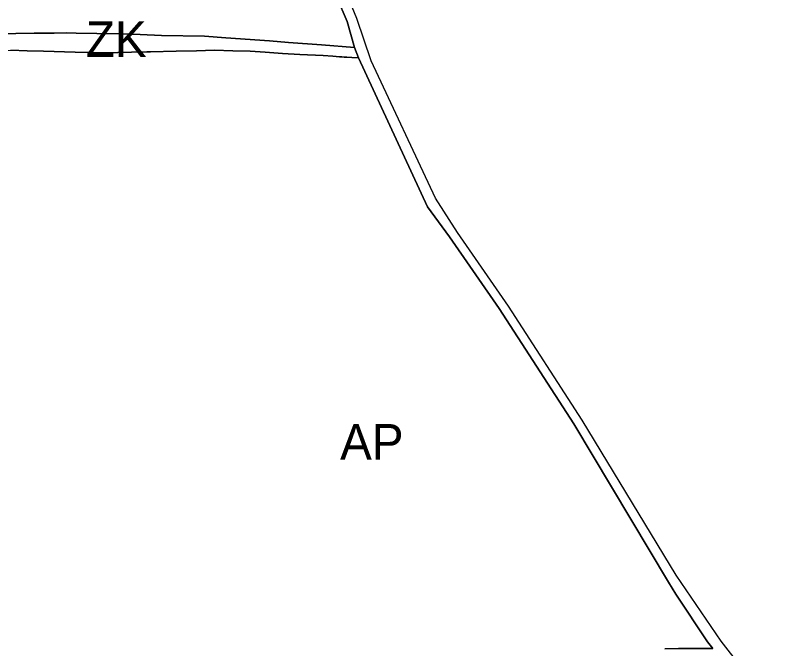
# Model space of a CAD drawing. Extents: x -555509 to -553005, y -1186756 to -1182560.
# Drawn here: x -553469.7 to -553167.8, y -1185141.6 to -1184892.4 of the extents above; entities that cross this region are included whole.
import ezdxf

# ---------------------------------------------------------------- set-up
doc = ezdxf.new("R2010")
doc.units = 0
for name, color, linetype in [('Level 26', 7, 'Continuous'), ('Level 59', 7, 'Continuous'), ('OBRYS_PLOCH', 7, 'Continuous'), ('stav_AP', 7, 'Continuous'), ('stav_AT', 7, 'Continuous'), ('stav_ZK', 7, 'Continuous')]:
    doc.layers.add(name, color=color, linetype=linetype)

msp = doc.modelspace()

# ---------------------------------------------------------------- linework, layer by layer
at = {"layer": 'Level 26'}
for p, q in [((-553335.3, -1184893.6), (-553358.23, -1184838.81)), ((-553350.74, -1184867.49), (-553339.19, -1184894.79)), ((-553339.19, -1184894.79), (-553336.3, -1184905.07)), ((-553336.3, -1184905.07), (-553334.72, -1184909.13)), ((-553334.72, -1184909.13), (-553307.56, -1184967.75)), ((-553307.56, -1184967.75), (-553298.83, -1184979.58)), ((-553275.71, -1185006.86), (-553295.78, -1184977.82)), ((-553298.83, -1184979.58), (-553279.36, -1185007.77)), ((-553279.36, -1185007.77), (-553249.97, -1185053.05)), ((-553246.62, -1185051.72), (-553275.71, -1185006.86)), ((-553249.97, -1185053.05), (-553212.7, -1185115.4)), ((-553212.7, -1185115.4), (-553209.78, -1185120.13)), ((-553209.78, -1185120.13), (-553197.3, -1185138.94)), ((-553167.79, -1185169.52), (-553192, -1185138.59)), ((-553208.75, -1185141.55), (-553214.16, -1185141.6)), ((-553203.3, -1185141.51), (-553208.75, -1185141.55)), ((-553199.65, -1185141.48), (-553203.3, -1185141.51)), ((-553195.31, -1185141.45), (-553199.65, -1185141.48)), ((-553197.3, -1185138.94), (-553195.31, -1185141.45))]:
    msp.add_line(p, q, dxfattribs=at)
for points in [[(-553295.78, -1184977.82), (-553304.44, -1184964.29), (-553329.69, -1184910.28), (-553335.3, -1184893.6)], [(-553192, -1185138.59), (-553209.69, -1185112.62), (-553246.62, -1185051.72)]]:
    msp.add_lwpolyline(points, dxfattribs=at)
at = {"layer": 'OBRYS_PLOCH'}
for p, q in [((-553335.3, -1184893.6), (-553358.23, -1184838.81)), ((-553350.74, -1184867.49), (-553339.19, -1184894.79)), ((-553339.19, -1184894.79), (-553350.74, -1184867.49)), ((-553339.19, -1184894.79), (-553336.3, -1184905.07)), ((-553336.3, -1184905.07), (-553339.19, -1184894.79)), ((-553462.29, -1184899.45), (-553479.59, -1184899.63)), ((-553479.59, -1184899.63), (-553462.29, -1184899.45)), ((-553454.39, -1184899.37), (-553462.29, -1184899.45)), ((-553462.29, -1184899.45), (-553454.39, -1184899.37)), ((-553449.74, -1184899.28), (-553454.39, -1184899.37)), ((-553454.39, -1184899.37), (-553449.74, -1184899.28)), ((-553445.86, -1184899.36), (-553449.74, -1184899.28)), ((-553449.74, -1184899.28), (-553445.86, -1184899.36)), ((-553437.62, -1184899.51), (-553445.86, -1184899.36)), ((-553445.86, -1184899.36), (-553437.62, -1184899.51)), ((-553429, -1184899.7), (-553437.62, -1184899.51)), ((-553437.62, -1184899.51), (-553429, -1184899.7)), ((-553420.65, -1184899.99), (-553429, -1184899.7)), ((-553429, -1184899.7), (-553420.65, -1184899.99)), ((-553412.24, -1184900.36), (-553420.65, -1184899.99)), ((-553420.65, -1184899.99), (-553412.24, -1184900.36)), ((-553395.32, -1184900.64), (-553412.24, -1184900.36)), ((-553412.24, -1184900.36), (-553395.32, -1184900.64)), ((-553386.89, -1184901.23), (-553395.32, -1184900.64)), ((-553395.32, -1184900.64), (-553386.89, -1184901.23)), ((-553369.75, -1184902.47), (-553386.89, -1184901.23)), ((-553386.89, -1184901.23), (-553369.75, -1184902.47)), ((-553362.23, -1184903.06), (-553369.75, -1184902.47)), ((-553369.75, -1184902.47), (-553362.23, -1184903.06)), ((-553349.3, -1184904.03), (-553362.23, -1184903.06)), ((-553362.23, -1184903.06), (-553349.3, -1184904.03)), ((-553336.3, -1184905.07), (-553349.3, -1184904.03)), ((-553349.3, -1184904.03), (-553336.3, -1184905.07)), ((-553334.72, -1184909.13), (-553336.3, -1184905.07)), ((-553336.3, -1184905.07), (-553334.72, -1184909.13)), ((-553424.01, -1184906.9), (-553418.01, -1184906.8)), ((-553418.01, -1184906.8), (-553424.01, -1184906.9)), ((-553334.72, -1184909.13), (-553307.56, -1184967.75)), ((-553307.56, -1184967.75), (-553298.83, -1184979.58)), ((-553275.71, -1185006.86), (-553295.78, -1184977.82)), ((-553298.83, -1184979.58), (-553279.36, -1185007.77)), ((-553279.36, -1185007.77), (-553249.97, -1185053.05)), ((-553246.62, -1185051.72), (-553275.71, -1185006.86)), ((-553249.97, -1185053.05), (-553212.7, -1185115.4)), ((-553212.7, -1185115.4), (-553209.78, -1185120.13)), ((-553209.78, -1185120.13), (-553197.3, -1185138.94)), ((-553167.79, -1185169.52), (-553192, -1185138.59)), ((-553208.75, -1185141.55), (-553214.16, -1185141.6)), ((-553203.3, -1185141.51), (-553208.75, -1185141.55)), ((-553199.65, -1185141.48), (-553203.3, -1185141.51)), ((-553195.31, -1185141.45), (-553199.65, -1185141.48)), ((-553197.3, -1185138.94), (-553195.31, -1185141.45))]:
    msp.add_line(p, q, dxfattribs=at)
for points in [[(-553295.78, -1184977.82), (-553304.44, -1184964.29), (-553329.69, -1184910.28), (-553335.3, -1184893.6)], [(-553507.59, -1184907.46), (-553501.65, -1184907.38), (-553496.76, -1184907.09), (-553491.68, -1184906.9), (-553488.86, -1184906.79), (-553486.02, -1184906.68), (-553481.61, -1184906.55), (-553476.49, -1184906.34), (-553471.51, -1184906.08), (-553465.03, -1184906.31), (-553458.67, -1184906.48), (-553446.15, -1184906.92), (-553434.79, -1184907.09), (-553424.01, -1184906.9)], [(-553424.01, -1184906.9), (-553434.79, -1184907.09), (-553446.15, -1184906.92), (-553458.67, -1184906.48), (-553465.03, -1184906.31), (-553471.51, -1184906.08)], [(-553418.01, -1184906.8), (-553416.51, -1184906.77), (-553406.42, -1184906.47), (-553398.4, -1184906.4), (-553391.31, -1184906.13), (-553384.13, -1184906.33), (-553377.34, -1184906.53), (-553371.36, -1184906.84), (-553364.62, -1184907.34), (-553357.77, -1184907.73), (-553348.61, -1184908.22), (-553344.76, -1184908.47), (-553343.45, -1184908.59), (-553342.15, -1184908.72), (-553341.24, -1184908.77), (-553340.33, -1184908.81), (-553339.24, -1184908.81), (-553337.26, -1184908.98), (-553334.72, -1184909.13)], [(-553209.78, -1185120.13), (-553212.7, -1185115.4), (-553249.97, -1185053.05), (-553279.36, -1185007.77), (-553298.83, -1184979.58), (-553307.56, -1184967.75), (-553334.72, -1184909.13), (-553337.26, -1184908.98), (-553339.24, -1184908.81), (-553340.33, -1184908.81), (-553341.24, -1184908.77), (-553342.15, -1184908.72), (-553343.45, -1184908.59), (-553344.76, -1184908.47), (-553348.61, -1184908.22), (-553357.77, -1184907.73), (-553364.62, -1184907.34), (-553371.36, -1184906.84), (-553377.34, -1184906.53), (-553384.13, -1184906.33), (-553391.31, -1184906.13), (-553398.4, -1184906.4), (-553406.42, -1184906.47), (-553416.51, -1184906.77), (-553418.01, -1184906.8)], [(-553192, -1185138.59), (-553209.69, -1185112.62), (-553246.62, -1185051.72)], [(-553214.16, -1185141.6), (-553208.75, -1185141.55), (-553203.3, -1185141.51), (-553199.65, -1185141.48), (-553195.31, -1185141.45), (-553197.3, -1185138.94), (-553209.78, -1185120.13)]]:
    msp.add_lwpolyline(points, dxfattribs=at)
at = {"layer": 'stav_AP'}
msp.add_line((-553418.01, -1184906.8), (-553424.01, -1184906.9), dxfattribs=at)
for points in [[(-553424.01, -1184906.9), (-553434.79, -1184907.09), (-553446.15, -1184906.92), (-553458.67, -1184906.48), (-553465.03, -1184906.31), (-553471.51, -1184906.08)], [(-553209.78, -1185120.13), (-553212.7, -1185115.4), (-553249.97, -1185053.05), (-553279.36, -1185007.77), (-553298.83, -1184979.58), (-553307.56, -1184967.75), (-553334.72, -1184909.13), (-553337.26, -1184908.98), (-553339.24, -1184908.81), (-553340.33, -1184908.81), (-553341.24, -1184908.77), (-553342.15, -1184908.72), (-553343.45, -1184908.59), (-553344.76, -1184908.47), (-553348.61, -1184908.22), (-553357.77, -1184907.73), (-553364.62, -1184907.34), (-553371.36, -1184906.84), (-553377.34, -1184906.53), (-553384.13, -1184906.33), (-553391.31, -1184906.13), (-553398.4, -1184906.4), (-553406.42, -1184906.47), (-553416.51, -1184906.77), (-553418.01, -1184906.8)], [(-553214.16, -1185141.6), (-553208.75, -1185141.55), (-553203.3, -1185141.51), (-553199.65, -1185141.48), (-553195.31, -1185141.45), (-553197.3, -1185138.94), (-553209.78, -1185120.13)]]:
    msp.add_lwpolyline(points, dxfattribs=at)
at = {"layer": 'stav_AT'}
for p, q in [((-553339.19, -1184894.79), (-553350.74, -1184867.49)), ((-553336.3, -1184905.07), (-553339.19, -1184894.79)), ((-553479.59, -1184899.63), (-553462.29, -1184899.45)), ((-553462.29, -1184899.45), (-553454.39, -1184899.37)), ((-553454.39, -1184899.37), (-553449.74, -1184899.28)), ((-553449.74, -1184899.28), (-553445.86, -1184899.36)), ((-553445.86, -1184899.36), (-553437.62, -1184899.51)), ((-553437.62, -1184899.51), (-553429, -1184899.7)), ((-553429, -1184899.7), (-553420.65, -1184899.99)), ((-553420.65, -1184899.99), (-553412.24, -1184900.36)), ((-553412.24, -1184900.36), (-553395.32, -1184900.64)), ((-553395.32, -1184900.64), (-553386.89, -1184901.23)), ((-553386.89, -1184901.23), (-553369.75, -1184902.47)), ((-553369.75, -1184902.47), (-553362.23, -1184903.06)), ((-553362.23, -1184903.06), (-553349.3, -1184904.03)), ((-553349.3, -1184904.03), (-553336.3, -1184905.07))]:
    msp.add_line(p, q, dxfattribs=at)
at = {"layer": 'stav_ZK'}
for p, q in [((-553462.29, -1184899.45), (-553479.59, -1184899.63)), ((-553454.39, -1184899.37), (-553462.29, -1184899.45)), ((-553449.74, -1184899.28), (-553454.39, -1184899.37)), ((-553445.86, -1184899.36), (-553449.74, -1184899.28)), ((-553437.62, -1184899.51), (-553445.86, -1184899.36)), ((-553429, -1184899.7), (-553437.62, -1184899.51)), ((-553420.65, -1184899.99), (-553429, -1184899.7)), ((-553412.24, -1184900.36), (-553420.65, -1184899.99)), ((-553395.32, -1184900.64), (-553412.24, -1184900.36)), ((-553386.89, -1184901.23), (-553395.32, -1184900.64)), ((-553369.75, -1184902.47), (-553386.89, -1184901.23)), ((-553362.23, -1184903.06), (-553369.75, -1184902.47)), ((-553349.3, -1184904.03), (-553362.23, -1184903.06)), ((-553336.3, -1184905.07), (-553349.3, -1184904.03)), ((-553334.72, -1184909.13), (-553336.3, -1184905.07)), ((-553424.01, -1184906.9), (-553418.01, -1184906.8))]:
    msp.add_line(p, q, dxfattribs=at)
for points in [[(-553507.59, -1184907.46), (-553501.65, -1184907.38), (-553496.76, -1184907.09), (-553491.68, -1184906.9), (-553488.86, -1184906.79), (-553486.02, -1184906.68), (-553481.61, -1184906.55), (-553476.49, -1184906.34), (-553471.51, -1184906.08), (-553465.03, -1184906.31), (-553458.67, -1184906.48), (-553446.15, -1184906.92), (-553434.79, -1184907.09), (-553424.01, -1184906.9)], [(-553418.01, -1184906.8), (-553416.51, -1184906.77), (-553406.42, -1184906.47), (-553398.4, -1184906.4), (-553391.31, -1184906.13), (-553384.13, -1184906.33), (-553377.34, -1184906.53), (-553371.36, -1184906.84), (-553364.62, -1184907.34), (-553357.77, -1184907.73), (-553348.61, -1184908.22), (-553344.76, -1184908.47), (-553343.45, -1184908.59), (-553342.15, -1184908.72), (-553341.24, -1184908.77), (-553340.33, -1184908.81), (-553339.24, -1184908.81), (-553337.26, -1184908.98), (-553334.72, -1184909.13)]]:
    msp.add_lwpolyline(points, dxfattribs=at)

# ---------------------------------------------------------------- texts
at = {"layer": 'Level 59'}
for s, p in [('ZK', (-553441.98, -1184908.78)), ('AP', (-553341.94, -1185067.2))]:
    msp.add_text(s, height=14, dxfattribs=at).set_placement(p)

doc.saveas('drawing.dxf')
